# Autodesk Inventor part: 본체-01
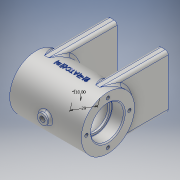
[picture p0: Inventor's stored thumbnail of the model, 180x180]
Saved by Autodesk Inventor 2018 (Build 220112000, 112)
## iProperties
Created: 2020-07
Part Number: 본체-01
Material: 알루미늄 6061
Document SubType Name: Modeling
Designer: home
Density: 2.7 g/cm^3
Appearance: 알루미늄 - 평지
Mass: 309.62 g
Surface Area: 371.462 cm^2
Volume: 114.674 cm^3
Author: home
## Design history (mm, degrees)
sketch "스케치1"
  geometry: L1 (26.26, 0)-(-26.26, 0); L2 (49.265, -16)-(37.265, -16); L3 (37.265, -16)-(37.265, -14); L4 (37.265, -14)-(35.265, -14); L5 (35.265, -14)-(35.265, -21); L6 (35.265, -21)-(-6.735, -21); L7 (-6.735, -21)-(-6.735, -14); L8 (-6.735, -14)-(-8.735, -14); L9 (-8.735, -14)-(-8.735, -16); L10 (-8.735, -16)-(-20.735, -16); L11 (-20.735, -16)-(-20.735, -26); L12 (-20.735, -26)-(49.265, -26); L13 (49.265, -26)-(49.265, -16); 2 further points
  constraints: 26 end point, 11 perpendicular, 2 horizontal, 1 coincident, 1 midpoint
  dimensions: "d0" = 32 diameter of L2 L1; "d1" = 2 distance between parallel lines of L5 L3; "d2" = 42 diameter of L6 L1; "d3" = 2 distance between parallel lines of L9 L7; "d4" = 32 diameter of L10 L1; "d5" = 52 diameter of L12 L1; "d6" = 70 distance between parallel lines of L11 L13; "d7" = 12 distance of L2.start L2.end; "d8" = 12 distance of L9.end L10.end; "d11" = 49.26497 distance from line of point (0, 0) L13; "d12" = 23.00528 distance from line of L1.start L13; "d88" = 28 diameter of L8 L1; "d89" = 28 diameter of L4 L1
revolve "회전1" sketch "스케치1" stored, may be unused: angle "d13" = 90 deg
node "작업 평면1"
sketch "스케치3"
  geometry: L1 (-20.735, 26)-(-20.735, -26) reference; L2 (-20.735, 26)-(-15.735, 26); L3 (49.265, 26)-(-20.735, 26) reference; L4 (49.265, 26)-(44.265, 26); L5 (44.265, 26)-(44.265, -26); L6 (44.265, -26)-(34.265, -26); L7 (34.265, -26)-(34.265, 26); L8 (-15.735, 26)-(-15.735, -26); L9 (-15.735, -26)-(-5.735, -26); L10 (-5.735, -26)-(-5.735, 26); 1 further point
  constraints: 16 end point, 5 perpendicular, 4 point on line
  dimensions: "d15" = 5 distance of L1.start L2.end; "d16" = 5 distance of L3.start L4.end; "d17" = 52 distance of L4.end L5.end; "d18" = 10 distance of L5.end L6.end; "d19" = 52 distance of L6.end L7.end; "d20" = 52 distance of L2.end L8.end; "d21" = 10 distance of L8.end L9.end
extrude "돌출1" join sketch "스케치3" stored distance "d22" = 10; taper "d23" = 0 deg
node "작업 평면2"
sketch "스케치4"
  geometry: L1 (-20.735, 26)-(-20.735, -26) reference; L2 (-20.735, 0)-(14.265, 0); C1 r 5 at (14.265, 0); 1 further point
  constraints: 2 end point, 1 centre point, 1 coincident, 1 horizontal, 1 midpoint
  dimensions: "d25" = 35 distance of L2.start L2.end; "d26" = 10 diameter of C1
extrude "돌출2" join sketch "스케치4" stored distance "d27" = 10; taper "d28" = 0 deg
sketch "스케치5"
  geometry: C1 r 5 at (14.265, 0) reference; 1 further point
hole "구멍1" sketch "스케치5" at (14.265, 0) diameter "d29" = 5.188; stored, may be unused: countersink angle "d33" = 90 deg, drill point angle "d35" = 118 deg; dims "d30" = 19, "d31" = 4, "d32" = 2, "d34" = 20
node "작업 평면3"
sketch "스케치6"
  geometry: L1 (0, 0)-(-9.919, 27.251); L2 (0, 0)-(29, 0)
  constraints: 4 end point, 1 equal length, 1 horizontal
  dimensions: "d36" = 29 distance of L1.start L1.end; "d37" = 110 deg angle of L2 L1
node "작업 평면4"
sketch "스케치7"
  geometry: C1 r 6 at (0, 0); 2 further points; 1 other entity
  constraints: 1 centre point, 1 other
  dimensions: "d38" = 12 diameter of C1; "d39" = 14.26497 distance of C1.centre point (-14.265, 0); "d40" = 9.91858 distance of point (0, -9.919) C1.centre
extrude "돌출3" join sketch "스케치7" stored distance "d41" = 10; taper "d42" = 0 deg
sketch "스케치8"
  geometry: C1 r 6 at (0, 0) reference; 2 further points
  constraints: 1 coincident
hole "구멍2" sketch "스케치8" at (0, 0) diameter "d43" = 5.188; stored, may be unused: countersink angle "d47" = 90 deg, drill point angle "d49" = 118 deg; dims "d44" = 12, "d45" = 4, "d46" = 2, "d48" = 16
sketch "스케치10"
  geometry: L1 (-49.265, -26)-(-49.265, 26) reference; L2 (-49.265, -26)-(-39.265, -26); L3 (-44.265, -26)-(-34.265, -26) reference; L4 (-39.265, -26)-(-39.265, -20); L5 (-39.265, -20)-(-39.265, 20); L6 (20.735, -26)-(20.735, 26) reference; L7 (20.735, -26)-(10.735, -26); L8 (5.735, -26)-(15.735, -26) reference; L9 (10.735, -26)-(10.735, -20); L10 (10.735, -20)-(10.735, 20); 3 further points
  constraints: 12 end point, 4 coincident, 4 vertical, 2 midpoint
  dimensions: "d50" = 10 distance of L1.start L2.end (derived); "d51" = 6 distance of L2.end L4.end; "d52" = 40 distance of L5.start L5.end; "d53" = 10 distance of L6.start L7.end (derived); "d54" = 6 distance of L7.end L9.end; "d55" = 40 distance of L10.start L10.end
hole "구멍3" sketch "스케치10" at (-39.265, 20), (-39.265, -20), (10.735, 20), (10.735, -20) diameter "d56" = 4.134; stored, may be unused: countersink angle "d60" = 90 deg, drill point angle "d62" = 118 deg; dims "d57" = 8, "d58" = 4, "d59" = 2, "d61" = 10
fillet "모깎기1" dims "d63" = 2, "d64" = 0.3, "d65" = 3, "d66" = 3
sketch "스케치11"
  geometry: A1 r 21 centre (0, 0) between (0, -21) and (-21, 0); 3 further points
  constraints: 4 point on circle, 1 centre point, 1 coincident
  dimensions: "d67" = 42 diameter of A1; "d68" = 29.69848 distance of point (21, 0) point (0, 21); "d69" = 29.69848 distance of point (21, 0) A1.start; "d70" = 42 distance of point (21, 0) A1.end; "d71" = 21 horizontal distance of A1.end A1.start
hole "구멍4" sketch "스케치11" at (0, -21), (-21, 0), (0, 21), (21, 0) diameter "d72" = 3.242; stored, may be unused: countersink angle "d76" = 90 deg, drill point angle "d78" = 118 deg; dims "d73" = 8, "d74" = 4, "d75" = 2, "d77" = 10
chamfer "모따기1" distance "d79" = 1; stored, may be unused: second distance "d80" = 2, angle "d81" = 45 deg
node "작업 평면5"
sketch "스케치12"
  geometry: L1 (20.735, -26)-(20.735, 26) reference; L2 (20.735, -26)-(-4.406, -26); L3 (-49.265, -26)-(20.735, -26) reference; 2 further points
  constraints: 2 end point, 1 point on line, 1 other
  dimensions: "d83" = 35 distance from line of L1 point (-14.265, 0); "d84" = 26 distance from line of point (-14.265, 0) L2; "d85" = 25.14117 distance from line of L2.end L1
feature "엠보싱1" sketch "스케치12" dims "d0" = 32, "d1" = 2, "d2" = 42, "d3" = 2, "d4" = 32, "d5" = 52, "d6" = 70, "d7" = 12, "d8" = 12, "d11" = 49.26497, "d12" = 23.00528, "d15" = 5, "d20" = 52, "d21" = 10, "d86" = 0.5, "d87" = 0, "d88" = 28, "d89" = 28
node "솔리드1"
mirror "미러1"
other parameters: "d14" = 64, "d24" = -29, "d82" = 26
